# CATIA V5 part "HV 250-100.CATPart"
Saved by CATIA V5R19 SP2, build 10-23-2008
Part number: HV 250-100
Bounding box of the stored display mesh (mm): x -18.951 to 18.951, y -18.952 to 18.952, z 0.053 to 269
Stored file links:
  C:\Users\Bora\Desktop\3D KATI MODEL- CATIA PART\HV serisi\HV 250\HV 250-100.CATPart
  C:\Program Files\Dassault Systemes\B19\intel_a\reffiles\standard\MetricThickPitch.txt
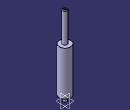
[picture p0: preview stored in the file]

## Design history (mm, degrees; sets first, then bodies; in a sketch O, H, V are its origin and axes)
Body1 (main body)
  Sketch1 on yz-plane, origin (0, 0, 0), H (0, 1, 0), V (0, 0, 1)
    point P1 (7.5, 267)
    point P3 (7.5, 267)
    point P7 (6, 17)
    point P8 (6, 1)
    point P10 (6, 1)
    point P12 (6, 17)
    line L1 (7.5, 267) -> (7.5, 168)
    arc A1 centre (5.5, 267) radius 2 from (7.5, 267) to (5.5, 269) ccw
    line L2 (6, 17) -> (6, 1)
    line L3 (5, 0) -> (6, 1)
    arc A2 centre (6, 18) radius 1 from (6, 19) to (6, 17) ccw
    line L4 (0, 0) -> (5, 0)
    line L5 (6, 19) -> (19, 19)
    line L6 (7.5, 168) -> (19, 168)
    line L7 (5.5, 269) -> (0, 269)
    point P13 (0, 269)
    line L8 (19, 168) -> (19, 19)
    horizontal: L4 H, L5 H, L6 H
    coincidence: P13 V, P1 P3, P7 P12, P8 P10
    tangency: L7 A1
    vertical: L8 V
  Shaft1: profile Sketch1, axis Sketch1.V, angle 360
  Sketch2 on face of Shaft1 from Sketch1.L4, origin (0, 0, 0), H (1, 0, 0), V (0, -1, 0)
    point P1 (0, 0)
  Hole1: placed by Sketch2, at (0, 0, 0) direction (0, 0, 1), diameter 10.106, depth 19, threaded "M12", thread diameter 12, thread depth 19, pitch 1.75
  Sketch3 on face of Shaft1 from Sketch1.L7, origin (0, 0, 269), H (1, 0, 0), V (0, 1, 0)
    point P1 (0, 0)
  Hole2: placed by Sketch3, at (0, 0, 269) direction (0, 0, -1), diameter 6.647, depth 15, threaded "M8", thread diameter 8, thread depth 15, pitch 1.25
